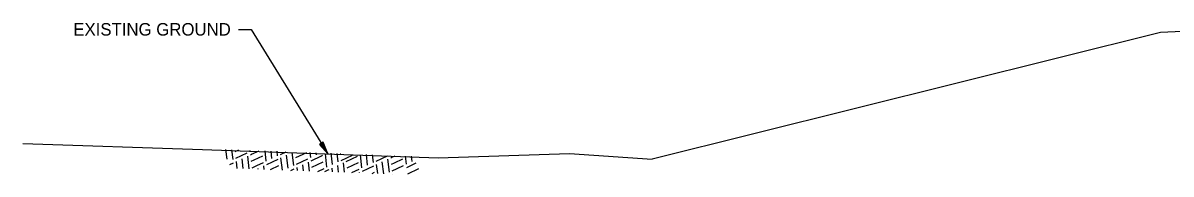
# Model space of a CAD drawing. Extents: x 1824008 to 1828864, y 689441 to 689870.
# Drawn here: x 1828714.3 to 1828769.2, y 689681.7 to 689688.9 of the extents above; entities that cross this region are included whole.
import ezdxf

# ---------------------------------------------------------------- set-up
doc = ezdxf.new("R2010")
doc.units = 0
doc.layers.add('1', color=7, linetype='Continuous')
doc.layers.add('R_Draft', color=7, linetype='Continuous')

msp = doc.modelspace()

# ---------------------------------------------------------------- linework, layer by layer
at = {"layer": '1'}
for p, q in [((1828768.706, 689688.47), (1828744.396, 689682.392)), ((1828770.706, 689688.55), (1828768.706, 689688.47)), ((1828724.062, 689682.39), (1828724.006, 689682.854)), ((1828724.062, 689682.39), (1828724.006, 689682.854)), ((1828724.062, 689682.39), (1828724.006, 689682.854)), ((1828724.351, 689682.372), (1828724.294, 689682.843)), ((1828724.351, 689682.372), (1828724.294, 689682.843)), ((1828724.351, 689682.372), (1828724.294, 689682.843)), ((1828724.448, 689682.75), (1828724.619, 689682.831)), ((1828724.448, 689682.75), (1828724.619, 689682.831)), ((1828724.448, 689682.75), (1828724.619, 689682.831)), ((1828725.164, 689682.758), (1828725.158, 689682.811)), ((1828725.164, 689682.758), (1828725.158, 689682.811)), ((1828725.164, 689682.758), (1828725.158, 689682.811)), ((1828725.228, 689682.622), (1828725.594, 689682.795)), ((1828725.228, 689682.622), (1828725.594, 689682.795)), ((1828725.228, 689682.622), (1828725.594, 689682.795)), ((1828725.937, 689682.294), (1828725.878, 689682.785)), ((1828725.937, 689682.294), (1828725.878, 689682.785)), ((1828725.937, 689682.294), (1828725.878, 689682.785)), ((1828726.208, 689682.422), (1828726.166, 689682.774)), ((1828726.208, 689682.422), (1828726.166, 689682.774)), ((1828726.208, 689682.422), (1828726.166, 689682.774)), ((1828726.479, 689682.551), (1828726.454, 689682.764)), ((1828726.479, 689682.551), (1828726.454, 689682.764)), ((1828726.479, 689682.551), (1828726.454, 689682.764)), ((1828724.186, 689682.128), (1828724.37, 689682.215)), ((1828724.186, 689682.128), (1828724.37, 689682.215)), ((1828724.186, 689682.128), (1828724.37, 689682.215)), ((1828724.486, 689682.436), (1828725.029, 689682.693)), ((1828724.486, 689682.436), (1828725.029, 689682.693)), ((1828724.486, 689682.436), (1828725.029, 689682.693)), ((1828724.546, 689681.946), (1828724.505, 689682.279)), ((1828724.546, 689681.946), (1828724.505, 689682.279)), ((1828724.546, 689681.946), (1828724.505, 689682.279)), ((1828724.834, 689681.936), (1828724.777, 689682.408)), ((1828724.834, 689681.936), (1828724.777, 689682.408)), ((1828724.834, 689681.936), (1828724.777, 689682.408)), ((1828725.122, 689681.925), (1828725.048, 689682.536)), ((1828725.122, 689681.925), (1828725.048, 689682.536)), ((1828725.122, 689681.925), (1828725.048, 689682.536)), ((1828725.183, 689682.601), (1828725.228, 689682.622)), ((1828725.183, 689682.601), (1828725.228, 689682.622)), ((1828725.183, 689682.601), (1828725.228, 689682.622)), ((1828725.221, 689682.287), (1828725.357, 689682.351)), ((1828725.221, 689682.287), (1828725.357, 689682.351)), ((1828725.221, 689682.287), (1828725.357, 689682.351)), ((1828725.357, 689682.351), (1828725.764, 689682.543)), ((1828725.357, 689682.351), (1828725.764, 689682.543)), ((1828725.357, 689682.351), (1828725.764, 689682.543)), ((1828725.485, 689682.08), (1828725.802, 689682.23)), ((1828725.485, 689682.08), (1828725.802, 689682.23)), ((1828725.485, 689682.08), (1828725.802, 689682.23)), ((1828725.956, 689682.137), (1828726.498, 689682.394)), ((1828725.956, 689682.137), (1828726.498, 689682.394)), ((1828725.956, 689682.137), (1828726.498, 689682.394)), ((1828726.615, 689682.615), (1828726.895, 689682.747)), ((1828726.615, 689682.615), (1828726.895, 689682.747)), ((1828726.615, 689682.615), (1828726.895, 689682.747)), ((1828726.706, 689681.866), (1828726.634, 689682.458)), ((1828726.706, 689681.866), (1828726.634, 689682.458)), ((1828726.706, 689681.866), (1828726.634, 689682.458)), ((1828726.981, 689681.958), (1828726.905, 689682.586)), ((1828726.981, 689681.958), (1828726.905, 689682.586)), ((1828726.981, 689681.958), (1828726.905, 689682.586)), ((1828727.252, 689682.087), (1828727.176, 689682.715)), ((1828727.252, 689682.087), (1828727.176, 689682.715)), ((1828727.35, 689682.465), (1828727.87, 689682.711)), ((1828727.35, 689682.465), (1828727.87, 689682.711)), ((1828727.35, 689682.465), (1828727.87, 689682.711)), ((1828727.388, 689682.151), (1828727.93, 689682.408)), ((1828727.388, 689682.151), (1828727.93, 689682.408)), ((1828727.388, 689682.151), (1828727.93, 689682.408)), ((1828728.002, 689681.819), (1828727.949, 689682.251)), ((1828728.002, 689681.819), (1828727.949, 689682.251)), ((1828728.002, 689681.819), (1828727.949, 689682.251)), ((1828728.066, 689682.472), (1828728.037, 689682.705)), ((1828728.066, 689682.472), (1828728.037, 689682.705)), ((1828728.066, 689682.472), (1828728.037, 689682.705)), ((1828728.085, 689682.315), (1828728.582, 689682.551)), ((1828728.085, 689682.315), (1828728.582, 689682.551)), ((1828728.085, 689682.315), (1828728.582, 689682.551)), ((1828728.123, 689682.001), (1828728.665, 689682.258)), ((1828728.123, 689682.001), (1828728.665, 689682.258)), ((1828728.123, 689682.001), (1828728.665, 689682.258)), ((1828728.337, 689682.601), (1828728.325, 689682.695)), ((1828728.337, 689682.601), (1828728.325, 689682.695)), ((1828728.337, 689682.601), (1828728.325, 689682.695)), ((1828728.582, 689682.551), (1828728.627, 689682.572)), ((1828728.582, 689682.551), (1828728.627, 689682.572)), ((1828728.582, 689682.551), (1828728.627, 689682.572)), ((1828728.839, 689682.008), (1828728.763, 689682.636)), ((1828728.839, 689682.008), (1828728.763, 689682.636)), ((1828728.839, 689682.008), (1828728.763, 689682.636)), ((1828729.11, 689682.137), (1828729.045, 689682.668)), ((1828729.11, 689682.137), (1828729.045, 689682.668)), ((1828729.11, 689682.137), (1828729.045, 689682.668)), ((1828729.381, 689682.265), (1828729.333, 689682.657)), ((1828729.381, 689682.265), (1828729.333, 689682.657)), ((1828729.381, 689682.265), (1828729.333, 689682.657)), ((1828729.478, 689682.643), (1828729.495, 689682.651)), ((1828729.478, 689682.643), (1828729.495, 689682.651)), ((1828729.478, 689682.643), (1828729.495, 689682.651)), ((1828729.516, 689682.329), (1828730.059, 689682.586)), ((1828729.516, 689682.329), (1828730.059, 689682.586)), ((1828729.516, 689682.329), (1828730.059, 689682.586)), ((1828729.681, 689681.757), (1828729.626, 689682.215)), ((1828729.681, 689681.757), (1828729.626, 689682.215)), ((1828729.681, 689681.757), (1828729.626, 689682.215)), ((1828729.761, 689682.28), (1828730.304, 689682.536)), ((1828729.761, 689682.28), (1828730.304, 689682.536)), ((1828729.761, 689682.28), (1828730.304, 689682.536)), ((1828729.799, 689681.966), (1828730.342, 689682.222)), ((1828729.799, 689681.966), (1828730.342, 689682.222)), ((1828729.799, 689681.966), (1828730.342, 689682.222)), ((1828730.515, 689681.973), (1828730.439, 689682.601)), ((1828730.515, 689681.973), (1828730.439, 689682.601)), ((1828730.515, 689681.973), (1828730.439, 689682.601)), ((1828730.786, 689682.101), (1828730.725, 689682.606)), ((1828730.786, 689682.101), (1828730.725, 689682.606)), ((1828730.786, 689682.101), (1828730.725, 689682.606)), ((1828731.058, 689682.23), (1828731.013, 689682.595)), ((1828731.058, 689682.23), (1828731.013, 689682.595)), ((1828731.058, 689682.23), (1828731.013, 689682.595)), ((1828731.193, 689682.294), (1828731.735, 689682.551)), ((1828731.193, 689682.294), (1828731.735, 689682.551)), ((1828731.193, 689682.294), (1828731.735, 689682.551)), ((1828731.553, 689681.687), (1828731.483, 689682.265)), ((1828731.553, 689681.687), (1828731.483, 689682.265)), ((1828731.553, 689681.687), (1828731.483, 689682.265)), ((1828731.83, 689681.766), (1828731.754, 689682.394)), ((1828731.83, 689681.766), (1828731.754, 689682.394)), ((1828731.83, 689681.766), (1828731.754, 689682.394)), ((1828731.89, 689682.458), (1828731.935, 689682.479)), ((1828731.89, 689682.458), (1828731.935, 689682.479)), ((1828731.89, 689682.458), (1828731.935, 689682.479)), ((1828731.935, 689682.479), (1828732.096, 689682.555)), ((1828731.935, 689682.479), (1828732.096, 689682.555)), ((1828731.935, 689682.479), (1828732.096, 689682.555)), ((1828732.064, 689682.208), (1828732.47, 689682.401)), ((1828732.064, 689682.208), (1828732.47, 689682.401)), ((1828732.064, 689682.208), (1828732.47, 689682.401)), ((1828732.644, 689682.151), (1828732.597, 689682.537)), ((1828732.644, 689682.151), (1828732.597, 689682.537)), ((1828732.644, 689682.151), (1828732.597, 689682.537)), ((1828732.915, 689682.28), (1828732.885, 689682.526)), ((1828732.915, 689682.28), (1828732.885, 689682.526)), ((1828732.915, 689682.28), (1828732.885, 689682.526)), ((1828725.259, 689681.973), (1828725.485, 689682.08)), ((1828725.259, 689681.973), (1828725.485, 689682.08)), ((1828725.259, 689681.973), (1828725.485, 689682.08)), ((1828725.554, 689681.909), (1828725.55, 689681.944)), ((1828725.554, 689681.909), (1828725.55, 689681.944)), ((1828725.554, 689681.909), (1828725.55, 689681.944)), ((1828725.842, 689681.898), (1828725.821, 689682.073)), ((1828725.842, 689681.898), (1828725.821, 689682.073)), ((1828725.842, 689681.898), (1828725.821, 689682.073)), ((1828726.131, 689681.888), (1828726.536, 689682.08)), ((1828726.131, 689681.888), (1828726.536, 689682.08)), ((1828726.131, 689681.888), (1828726.536, 689682.08)), ((1828727.106, 689681.852), (1828727.271, 689681.93)), ((1828727.106, 689681.852), (1828727.271, 689681.93)), ((1828727.106, 689681.852), (1828727.271, 689681.93)), ((1828727.426, 689681.84), (1828727.407, 689681.994)), ((1828727.426, 689681.84), (1828727.407, 689681.994)), ((1828727.426, 689681.84), (1828727.407, 689681.994)), ((1828727.714, 689681.829), (1828727.678, 689682.123)), ((1828727.714, 689681.829), (1828727.678, 689682.123)), ((1828727.714, 689681.829), (1828727.678, 689682.123)), ((1828728.406, 689681.804), (1828728.703, 689681.944)), ((1828728.406, 689681.804), (1828728.703, 689681.944)), ((1828728.406, 689681.804), (1828728.703, 689681.944)), ((1828728.731, 689681.792), (1828728.903, 689681.873)), ((1828728.731, 689681.792), (1828728.903, 689681.873)), ((1828728.731, 689681.792), (1828728.903, 689681.873)), ((1828728.903, 689681.873), (1828728.948, 689681.894)), ((1828728.903, 689681.873), (1828728.948, 689681.894)), ((1828728.903, 689681.873), (1828728.948, 689681.894)), ((1828729.106, 689681.778), (1828729.084, 689681.958)), ((1828729.106, 689681.778), (1828729.084, 689681.958)), ((1828729.106, 689681.778), (1828729.084, 689681.958)), ((1828729.393, 689681.767), (1828729.355, 689682.087)), ((1828729.393, 689681.767), (1828729.355, 689682.087)), ((1828729.393, 689681.767), (1828729.355, 689682.087)), ((1828730.032, 689681.744), (1828730.38, 689681.909)), ((1828730.032, 689681.744), (1828730.38, 689681.909)), ((1828730.032, 689681.744), (1828730.38, 689681.909)), ((1828730.401, 689681.73), (1828730.399, 689681.752)), ((1828730.401, 689681.73), (1828730.399, 689681.752)), ((1828730.401, 689681.73), (1828730.399, 689681.752)), ((1828730.534, 689681.816), (1828731.077, 689682.073)), ((1828730.534, 689681.816), (1828731.077, 689682.073)), ((1828730.534, 689681.816), (1828731.077, 689682.073)), ((1828731.007, 689681.708), (1828731.115, 689681.759)), ((1828731.007, 689681.708), (1828731.115, 689681.759)), ((1828731.007, 689681.708), (1828731.115, 689681.759)), ((1828731.265, 689681.698), (1828731.212, 689682.137)), ((1828731.265, 689681.698), (1828731.212, 689682.137)), ((1828731.265, 689681.698), (1828731.212, 689682.137)), ((1828731.928, 689682.144), (1828732.064, 689682.208)), ((1828731.928, 689682.144), (1828732.064, 689682.208)), ((1828731.928, 689682.144), (1828732.064, 689682.208)), ((1828731.966, 689681.83), (1828732.192, 689681.937)), ((1828731.966, 689681.83), (1828732.192, 689681.937)), ((1828731.966, 689681.83), (1828732.192, 689681.937)), ((1828731.985, 689681.671), (1828731.985, 689681.673)), ((1828731.985, 689681.671), (1828731.985, 689681.673)), ((1828731.985, 689681.671), (1828731.985, 689681.673)), ((1828732.192, 689681.937), (1828732.508, 689682.087)), ((1828732.192, 689681.937), (1828732.508, 689682.087)), ((1828732.192, 689681.937), (1828732.508, 689682.087)), ((1828732.663, 689681.994), (1828733.11, 689682.206)), ((1828732.663, 689681.994), (1828733.11, 689682.206)), ((1828732.663, 689681.994), (1828733.11, 689682.206)), ((1828732.701, 689681.68), (1828733.239, 689681.935)), ((1828732.701, 689681.68), (1828733.239, 689681.935)), ((1828732.701, 689681.68), (1828733.239, 689681.935))]:
    msp.add_line(p, q, dxfattribs=at)
msp.add_lwpolyline([(1828714.298, 689683.135), (1828722.881, 689682.845), (1828734.166, 689682.459), (1828740.435, 689682.652), (1828744.396, 689682.392)], dxfattribs=at)
at = {"layer": 'R_Draft'}
for p, q in [((1828724.062, 689682.39), (1828724.006, 689682.854)), ((1828724.351, 689682.372), (1828724.294, 689682.843)), ((1828724.448, 689682.75), (1828724.619, 689682.831)), ((1828725.164, 689682.758), (1828725.158, 689682.811)), ((1828725.228, 689682.622), (1828725.594, 689682.795)), ((1828725.937, 689682.294), (1828725.878, 689682.785)), ((1828726.208, 689682.422), (1828726.166, 689682.774)), ((1828726.479, 689682.551), (1828726.454, 689682.764)), ((1828728.66, 689683.207), (1828728.482, 689683.097)), ((1828728.482, 689683.097), (1828728.883, 689682.64)), ((1828728.523, 689683.118), (1828728.787, 689682.769)), ((1828728.809, 689682.781), (1828728.617, 689683.174)), ((1828728.883, 689682.64), (1828728.66, 689683.207)), ((1828724.186, 689682.128), (1828724.37, 689682.215)), ((1828724.486, 689682.436), (1828725.029, 689682.693)), ((1828724.546, 689681.946), (1828724.505, 689682.279)), ((1828724.834, 689681.936), (1828724.777, 689682.408)), ((1828725.122, 689681.925), (1828725.048, 689682.536)), ((1828725.183, 689682.601), (1828725.228, 689682.622)), ((1828725.221, 689682.287), (1828725.357, 689682.351)), ((1828725.357, 689682.351), (1828725.764, 689682.543)), ((1828725.485, 689682.08), (1828725.802, 689682.23)), ((1828725.956, 689682.137), (1828726.498, 689682.394)), ((1828726.615, 689682.615), (1828726.895, 689682.747)), ((1828726.706, 689681.866), (1828726.634, 689682.458)), ((1828726.981, 689681.958), (1828726.905, 689682.586)), ((1828727.252, 689682.087), (1828727.176, 689682.715)), ((1828727.35, 689682.465), (1828727.87, 689682.711)), ((1828727.388, 689682.151), (1828727.93, 689682.408)), ((1828728.002, 689681.819), (1828727.949, 689682.251)), ((1828728.066, 689682.472), (1828728.037, 689682.705)), ((1828728.085, 689682.315), (1828728.582, 689682.551)), ((1828728.123, 689682.001), (1828728.665, 689682.258)), ((1828728.337, 689682.601), (1828728.325, 689682.695)), ((1828728.582, 689682.551), (1828728.627, 689682.572)), ((1828728.839, 689682.008), (1828728.763, 689682.636)), ((1828729.11, 689682.137), (1828729.045, 689682.668)), ((1828729.381, 689682.265), (1828729.333, 689682.657)), ((1828729.478, 689682.643), (1828729.495, 689682.651)), ((1828729.516, 689682.329), (1828730.059, 689682.586)), ((1828729.681, 689681.757), (1828729.626, 689682.215)), ((1828729.761, 689682.28), (1828730.304, 689682.536)), ((1828729.799, 689681.966), (1828730.342, 689682.222)), ((1828730.515, 689681.973), (1828730.439, 689682.601)), ((1828730.786, 689682.101), (1828730.725, 689682.606)), ((1828731.058, 689682.23), (1828731.013, 689682.595)), ((1828731.193, 689682.294), (1828731.735, 689682.551)), ((1828731.553, 689681.687), (1828731.483, 689682.265)), ((1828731.83, 689681.766), (1828731.754, 689682.394)), ((1828731.89, 689682.458), (1828731.935, 689682.479)), ((1828731.935, 689682.479), (1828732.096, 689682.555)), ((1828732.064, 689682.208), (1828732.47, 689682.401)), ((1828732.644, 689682.151), (1828732.597, 689682.537)), ((1828732.915, 689682.28), (1828732.885, 689682.526)), ((1828725.259, 689681.973), (1828725.485, 689682.08)), ((1828725.554, 689681.909), (1828725.55, 689681.944)), ((1828725.842, 689681.898), (1828725.821, 689682.073)), ((1828726.131, 689681.888), (1828726.536, 689682.08)), ((1828727.106, 689681.852), (1828727.271, 689681.93)), ((1828727.426, 689681.84), (1828727.407, 689681.994)), ((1828727.714, 689681.829), (1828727.678, 689682.123)), ((1828728.406, 689681.804), (1828728.703, 689681.944)), ((1828728.731, 689681.792), (1828728.903, 689681.873)), ((1828728.903, 689681.873), (1828728.948, 689681.894)), ((1828729.106, 689681.778), (1828729.084, 689681.958)), ((1828729.393, 689681.767), (1828729.355, 689682.087)), ((1828730.032, 689681.744), (1828730.38, 689681.909)), ((1828730.401, 689681.73), (1828730.399, 689681.752)), ((1828730.534, 689681.816), (1828731.077, 689682.073)), ((1828731.007, 689681.708), (1828731.115, 689681.759)), ((1828731.265, 689681.698), (1828731.212, 689682.137)), ((1828731.928, 689682.144), (1828732.064, 689682.208)), ((1828731.966, 689681.83), (1828732.192, 689681.937)), ((1828731.985, 689681.671), (1828731.985, 689681.673)), ((1828732.192, 689681.937), (1828732.508, 689682.087)), ((1828732.663, 689681.994), (1828733.11, 689682.206)), ((1828732.701, 689681.68), (1828733.239, 689681.935))]:
    msp.add_line(p, q, dxfattribs=at)
msp.add_lwpolyline([(1828724.607, 689688.616), (1828725.207, 689688.616), (1828728.883, 689682.64)], dxfattribs=at)

# ---------------------------------------------------------------- texts
msp.add_text('EXISTING GROUND', height=0.6, dxfattribs=at).set_placement((1828716.706, 689688.316))

doc.saveas('drawing.dxf')
